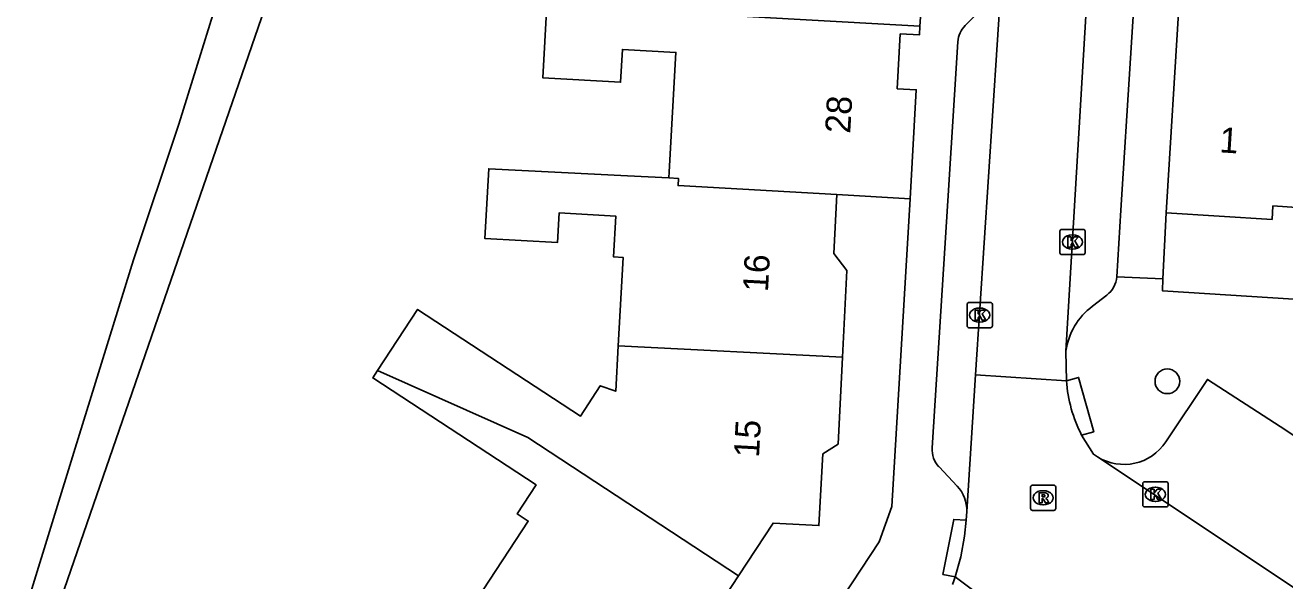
# Model space of a CAD drawing. Extents: x 159280 to 160375, y 384531 to 385872.
# Drawn here: x 160006.07 to 160056.02, y 384704.43 to 384726.45 of the extents above; entities that cross this region are included whole.
import ezdxf

# ---------------------------------------------------------------- set-up
doc = ezdxf.new("R2010")
doc.units = 0
for name, color, linetype in [('IMGEO_Boom', 7, 'Continuous'), ('IMGEO_Kolk', 7, 'Continuous'), ('IMGEO_Pand', 7, 'Continuous'), ('IMGEO_Pand_nummerreeks', 7, 'Continuous'), ('IMGEO_Rijbaan_lokaal_open', 7, 'Continuous'), ('IMGEO_Rioolput', 7, 'Continuous'), ('IMGEO_Voetpad_open', 7, 'Continuous')]:
    doc.layers.add(name, color=color, linetype=linetype)

msp = doc.modelspace()

# ---------------------------------------------------------------- linework, layer by layer
at = {"layer": 'IMGEO_Boom'}
msp.add_circle((160051.365, 384712.336), 0.489, dxfattribs=at)
at = {"layer": 'IMGEO_Kolk'}
for p, q in [((160047.101, 384717.429), (160047.101, 384718.281)), ((160047.176, 384718.355), (160048.028, 384718.355)), ((160048.102, 384718.281), (160048.102, 384717.429)), ((160047.589, 384718.135), (160047.614, 384718.135)), ((160048.028, 384717.355), (160047.176, 384717.355)), ((160047.612, 384717.575), (160047.587, 384717.575)), ((160043.423, 384714.534), (160043.423, 384715.386)), ((160043.498, 384715.46), (160044.35, 384715.46)), ((160043.911, 384715.24), (160043.936, 384715.24)), ((160044.424, 384715.386), (160044.424, 384714.534)), ((160044.35, 384714.46), (160043.498, 384714.46)), ((160043.934, 384714.68), (160043.909, 384714.68)), ((160050.392, 384707.431), (160050.392, 384708.283)), ((160050.467, 384708.357), (160051.319, 384708.357)), ((160051.393, 384708.283), (160051.393, 384707.431)), ((160050.88, 384708.137), (160050.905, 384708.137)), ((160051.319, 384707.357), (160050.467, 384707.357)), ((160050.903, 384707.577), (160050.878, 384707.577))]:
    msp.add_line(p, q, dxfattribs=at)
for points in [[(160047.101, 384717.429), (160047.101, 384718.281)], [(160047.176, 384718.355), (160048.028, 384718.355)], [(160048.102, 384718.281), (160048.102, 384717.429)], [(160047.422, 384718.055), (160047.545, 384718.055), (160047.545, 384717.904), (160047.675, 384718.055), (160047.839, 384718.055), (160047.693, 384717.904), (160047.846, 384717.655), (160047.694, 384717.655), (160047.609, 384717.819), (160047.545, 384717.752), (160047.545, 384717.655), (160047.422, 384717.655), (160047.422, 384718.055)], [(160048.028, 384717.355), (160047.176, 384717.355)], [(160043.423, 384714.534), (160043.423, 384715.386)], [(160043.498, 384715.46), (160044.35, 384715.46)], [(160044.424, 384715.386), (160044.424, 384714.534)], [(160043.744, 384715.16), (160043.867, 384715.16), (160043.867, 384715.009), (160043.997, 384715.16), (160044.161, 384715.16), (160044.015, 384715.009), (160044.168, 384714.76), (160044.016, 384714.76), (160043.931, 384714.924), (160043.867, 384714.857), (160043.867, 384714.76), (160043.744, 384714.76), (160043.744, 384715.16)], [(160044.35, 384714.46), (160043.498, 384714.46)], [(160050.392, 384707.431), (160050.392, 384708.283)], [(160050.467, 384708.357), (160051.319, 384708.357)], [(160051.393, 384708.283), (160051.393, 384707.431)], [(160050.713, 384708.057), (160050.836, 384708.057), (160050.836, 384707.906), (160050.966, 384708.057), (160051.13, 384708.057), (160050.984, 384707.906), (160051.137, 384707.657), (160050.985, 384707.657), (160050.9, 384707.821), (160050.836, 384707.754), (160050.836, 384707.657), (160050.713, 384707.657), (160050.713, 384708.057)], [(160051.319, 384707.357), (160050.467, 384707.357)]]:
    msp.add_lwpolyline(points, dxfattribs=at)
for centre, start, end in [((160047.178, 384718.279), 91.552, 178.448), ((160047.178, 384718.279), 91.552, 178.448), ((160048.026, 384718.279), 1.552, 88.448), ((160048.026, 384718.279), 1.552, 88.448), ((160047.178, 384717.431), 181.552, 268.448), ((160047.178, 384717.431), 181.552, 268.448), ((160048.026, 384717.431), 271.552, 358.448), ((160048.026, 384717.431), 271.552, 358.448), ((160043.5, 384715.384), 91.552, 178.448), ((160043.5, 384715.384), 91.552, 178.448), ((160044.348, 384715.384), 1.552, 88.448), ((160044.348, 384715.384), 1.552, 88.448), ((160043.5, 384714.536), 181.552, 268.448), ((160043.5, 384714.536), 181.552, 268.448), ((160044.348, 384714.536), 271.552, 358.448), ((160044.348, 384714.536), 271.552, 358.448), ((160050.469, 384708.281), 91.552, 178.448), ((160050.469, 384708.281), 91.552, 178.448), ((160051.317, 384708.281), 1.552, 88.448), ((160051.317, 384708.281), 1.552, 88.448), ((160050.469, 384707.433), 181.552, 268.448), ((160050.469, 384707.433), 181.552, 268.448), ((160051.317, 384707.433), 271.552, 358.448), ((160051.317, 384707.433), 271.552, 358.448)]:
    msp.add_arc(centre, 0.0765, start, end, dxfattribs=at)
for centre, major_axis, ratio, start_param, end_param in [((160047.588, 384717.855), (-0.387, 0.002), 0.722429, 4.712389, 7.853982), ((160047.613, 384717.855), (-0.39, 0.002), 0.717154, 1.570796, 4.712389), ((160043.91, 384714.96), (-0.387, 0.002), 0.722429, 4.712389, 7.853982), ((160043.935, 384714.96), (-0.39, 0.002), 0.717154, 1.570796, 4.712389), ((160050.879, 384707.857), (-0.387, 0.002), 0.722429, 4.712389, 7.853982), ((160050.904, 384707.857), (-0.39, 0.002), 0.717154, 1.570796, 4.712389)]:
    msp.add_ellipse(centre, major_axis=major_axis, ratio=ratio, start_param=start_param, end_param=end_param, dxfattribs=at)
at = {"layer": 'IMGEO_Pand'}
for points in [[(160031.594, 384720.394), (160031.608, 384720.638), (160031.875, 384725.365), (160029.752, 384725.485), (160029.678, 384724.184), (160026.597, 384724.358), (160026.76, 384727.243)], [(160026.76, 384727.243), (160036.563, 384726.689), (160041.555, 384726.407)], [(160051.315, 384719.018), (160051.838, 384727.361)], [(160041.555, 384726.407), (160041.535, 384726.061), (160040.773, 384726.104), (160040.65, 384723.93), (160041.407, 384723.887), (160041.163, 384719.572)], [(160029.586, 384713.74), (160029.784, 384717.241), (160029.4, 384717.263), (160029.491, 384718.884), (160027.243, 384719.011), (160027.176, 384717.833), (160024.295, 384717.996), (160024.451, 384720.758), (160029.952, 384720.478), (160031.594, 384720.394)], [(160031.594, 384720.394), (160031.976, 384720.375), (160031.96, 384720.092), (160038.257, 384719.737)], [(160038.257, 384719.737), (160038.132, 384717.405), (160038.654, 384716.727), (160038.479, 384713.288)], [(160041.163, 384719.572), (160038.257, 384719.737)], [(160056.873, 384719.2), (160055.552, 384719.283), (160055.519, 384718.754), (160051.315, 384719.018)], [(160020.038, 384712.758), (160021.627, 384715.183), (160028.084, 384710.953), (160028.876, 384712.162), (160029.485, 384711.944), (160029.586, 384713.74)], [(160029.586, 384713.74), (160038.479, 384713.288)], [(160038.479, 384713.288), (160038.305, 384709.851), (160037.707, 384709.459), (160037.546, 384706.619), (160035.726, 384706.722), (160034.354, 384704.627)], [(160023.982, 384703.687), (160026.018, 384706.795), (160025.579, 384707.083), (160026.329, 384708.229), (160019.851, 384712.473), (160020.038, 384712.758)], [(160034.354, 384704.627), (160026.003, 384710.105), (160020.038, 384712.758)], [(160034.354, 384704.627), (160032.982, 384702.534), (160033.136, 384701.794), (160031.254, 384698.921)]]:
    msp.add_lwpolyline(points, dxfattribs=at)
at = {"layer": 'IMGEO_Rijbaan_lokaal_open'}
for points in [[(160047.342, 384713.529), (160048.469, 384732.359), (160048.973, 384740.135)], [(160044.785, 384728.292), (160043.761, 384712.594)], [(160047.362, 384712.359), (160047.342, 384713.529)], [(160043.761, 384712.594), (160043.408, 384707.174)], [(160043.761, 384712.594), (160047.362, 384712.359)], [(160048.596, 384709.338), (160048.433, 384709.443), (160047.964, 384710.204)], [(160063.252, 384699.583), (160048.596, 384709.338)], [(160043.386, 384706.838), (160043.321, 384706.199), (160043.173, 384705.384), (160042.952, 384704.585)], [(160043.408, 384707.174), (160043.386, 384706.838)], [(160042.952, 384704.585), (160042.901, 384704.432), (160042.847, 384704.28)], [(160042.952, 384704.585), (160046.715, 384701.757)]]:
    msp.add_lwpolyline(points, dxfattribs=at)
msp.add_arc((160052.971, 384712.764), 5.624, 184.1339, 207.0816, dxfattribs=at)
at = {"layer": 'IMGEO_Rioolput'}
for p, q in [((160046.014, 384708.221), (160046.866, 384708.221)), ((160045.939, 384707.295), (160045.939, 384708.147)), ((160046.427, 384708.001), (160046.452, 384708.001)), ((160046.94, 384708.147), (160046.94, 384707.295)), ((160046.866, 384707.221), (160046.014, 384707.221)), ((160046.45, 384707.441), (160046.425, 384707.441))]:
    msp.add_line(p, q, dxfattribs=at)
for points in [[(160046.014, 384708.221), (160046.866, 384708.221)], [(160045.939, 384707.295), (160045.939, 384708.147)], [(160046.528, 384707.919), (160046.276, 384707.921), (160046.276, 384707.521)], [(160046.454, 384707.84), (160046.4, 384707.84), (160046.4, 384707.759)], [(160046.4, 384707.759), (160046.452, 384707.759)], [(160046.94, 384708.147), (160046.94, 384707.295)], [(160046.866, 384707.221), (160046.014, 384707.221)], [(160046.276, 384707.521), (160046.4, 384707.521), (160046.4, 384707.683), (160046.411, 384707.683)], [(160046.458, 384707.654), (160046.529, 384707.521), (160046.669, 384707.521), (160046.604, 384707.647)]]:
    msp.add_lwpolyline(points, dxfattribs=at)
for centre, radius, start, end in [((160046.016, 384708.145), 0.0765, 91.552, 178.448), ((160046.016, 384708.145), 0.0765, 91.552, 178.448), ((160046.864, 384708.145), 0.0765, 1.552, 88.448), ((160046.864, 384708.145), 0.0765, 1.552, 88.448), ((160046.436, 384707.948), 0.19, 274.7715, 282.9687), ((160046.46, 384707.744), 0.0964, 77.0061, 93.1865), ((160046.474, 384707.801), 0.0378, 276.6634, 79.6772), ((160046.527, 384707.809), 0.109, 350.3612, 89.416), ((160046.525, 384707.809), 0.112, 277.5842, 350.9817), ((160046.509, 384707.594), 0.108, 29.5134, 73.7905), ((160046.016, 384707.297), 0.0765, 181.552, 268.448), ((160046.016, 384707.297), 0.0765, 181.552, 268.448), ((160046.41, 384707.63), 0.0533, 26.0293, 88.6989), ((160046.864, 384707.297), 0.0765, 271.552, 358.448), ((160046.864, 384707.297), 0.0765, 271.552, 358.448)]:
    msp.add_arc(centre, radius, start, end, dxfattribs=at)
for centre, major_axis, ratio, start_param, end_param in [((160046.426, 384707.721), (-0.387, 0.002), 0.722429, 4.712389, 7.853982), ((160046.451, 384707.721), (-0.39, 0.002), 0.717154, 1.570796, 4.712389)]:
    msp.add_ellipse(centre, major_axis=major_axis, ratio=ratio, start_param=start_param, end_param=end_param, dxfattribs=at)
at = {"layer": 'IMGEO_Voetpad_open'}
for points in [[(160050.671, 384737.196), (160049.523, 384719.116), (160049.356, 384716.481)], [(160003.706, 384731.724), (160014.148, 384730.2), (160014.315, 384729.455), (160012.16, 384722.524), (160010.366, 384717.15), (160008.046, 384709.688), (160006.275, 384703.947), (160005.914, 384704.059), (160003.497, 384696.526), (160002.619, 384693.786)], [(160002.494, 384686.271), (160003.116, 384691.117), (160015.824, 384727.861), (160026.76, 384727.243)], [(160041.555, 384726.407), (160041.666, 384728.061)], [(160044.252, 384727.319), (160043.353, 384726.435)], [(160043.056, 384725.785), (160042.658, 384719.49), (160042.039, 384709.697)], [(160041.163, 384719.572), (160040.444, 384707.372), (160039.931, 384705.971), (160020.662, 384676.735)], [(160051.19, 384716.394), (160051.315, 384719.018)], [(160049.356, 384716.481), (160051.19, 384716.394)], [(160051.19, 384716.394), (160051.168, 384715.923), (160056.386, 384715.596), (160065.194, 384709.878), (160067.744, 384704.931), (160070.36, 384706.402)], [(160048.968, 384715.753), (160048.394, 384715.31)], [(160047.362, 384712.359), (160047.843, 384712.492), (160048.445, 384710.337), (160047.964, 384710.204)], [(160051.308, 384709.935), (160052.954, 384712.41), (160055.843, 384710.546), (160064.943, 384704.496), (160063.004, 384701.572)], [(160042.309, 384708.949), (160043.028, 384708.185)], [(160042.952, 384704.585), (160042.462, 384704.682), (160042.891, 384706.866), (160043.386, 384706.838)]]:
    msp.add_lwpolyline(points, dxfattribs=at)
for centre, radius, start, end in [((160044.037, 384725.729), 0.983, 134.1274, 176.7591), ((160048.359, 384716.545), 0.999, 307.5512, 356.3365), ((160049.998, 384713.161), 2.682, 126.7453, 172.1158), ((160043.027, 384709.631), 0.991, 176.1824, 223.513), ((160049.643, 384711.042), 1.999, 238.4335, 326.3958), ((160041.998, 384707.221), 1.411, 358.1004, 43.0986)]:
    msp.add_arc(centre, radius, start, end, dxfattribs=at)

# ---------------------------------------------------------------- texts
at = {"layer": 'IMGEO_Pand_nummerreeks'}
for s, rotation, p in [('28', 86.7172, (160038.786, 384722.138)), ('1', 356.4067, (160053.414, 384721.411)), ('16', 86.8948, (160035.524, 384715.858)), ('15', 86.8971, (160035.168, 384709.3))]:
    msp.add_text(s, height=1, rotation=rotation, dxfattribs=at).set_placement(p)

doc.saveas('drawing.dxf')
